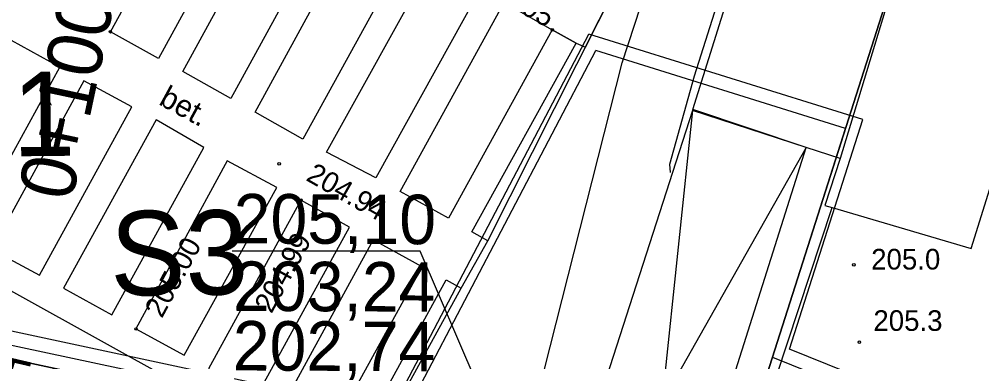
# Model space of a CAD drawing. Extents: x 6512606 to 6513347, y 6022524 to 6022728.
# Drawn here: x 6512758.91 to 6512793.86, y 6022598.41 to 6022610.86 of the extents above; entities that cross this region are included whole.
import ezdxf

# ---------------------------------------------------------------- set-up
doc = ezdxf.new("R2010")
doc.units = 0
for name, color, linetype in [('20', 7, 'Continuous'), ('217-kontur klasyfikacyjny', 7, 'Continuous'), ('218-kontur użytku gruntowego', 7, 'Continuous'), ('219-działka ewidencyjna', 7, 'Continuous'), ('312-budynek ewidencyjny', 7, 'Continuous'), ('4', 7, 'Continuous'), ('996-Tekst dodatkowy mały', 7, 'Continuous'), ('budynek', 7, 'Continuous'), ('chodnik', 7, 'Continuous'), ('chodnik (powierzchnia)', 7, 'Continuous'), ('Default', 7, 'Continuous'), ('kolor_kostka_bet', 7, 'Continuous'), ('Level 47', 7, 'Continuous'), ('maxp_inst_wodociągowa', 7, 'Continuous'), ('maxp_likwidacje', 7, 'Continuous'), ('maxp_ramka_2', 7, 'Continuous'), ('ogrodzenie trwałe', 7, 'Continuous'), ('pikieta naturalna', 7, 'Continuous'), ('pikieta naturalna-Atr2', 7, 'Continuous'), ('pikieta sztuczna', 7, 'Continuous'), ('pikieta sztuczna-Atr2', 7, 'Continuous'), ('przewód elektroenergetyczny (linia)', 7, 'Continuous'), ('przewód kanalizacyjny (linia)', 7, 'Continuous'), ('psr_os', 7, 'Continuous'), ('punkt wysokościowy naturalny', 7, 'Continuous'), ('punkt wysokościowy naturalny-Atr2', 7, 'Continuous'), ('punkt wysokościowy sztuczny', 7, 'Continuous'), ('punkt wysokościowy sztuczny-Atr2', 7, 'Continuous')]:
    doc.layers.add(name, color=color, linetype=linetype)

# ---------------------------------------------------------------- blocks, each defined once
blk = doc.blocks.new('PW01')
at = {"layer": 'Default'}
blk.add_circle((0, 0), 0.45, dxfattribs=at)
blk = doc.blocks.new('PW02')
at = {"layer": 'Default'}
blk.add_circle((0, 0), 0.45, dxfattribs=at)

msp = doc.modelspace()

# ---------------------------------------------------------------- linework, layer by layer
msp.add_line((6512749.181, 6022600.515), (6512804.476, 6022588.74))
at = {"layer": '20'}
for p, q in [((6512773.476, 6022602.425), (6512766.642, 6022602.425)), ((6512777.689, 6022592.612), (6512773.476, 6022602.425))]:
    msp.add_line(p, q, dxfattribs=at)
at = {"layer": '217-kontur klasyfikacyjny'}
msp.add_lwpolyline([(6512784.22, 6022592.17), (6512791.71, 6022615.65)], dxfattribs=at)
at = {"layer": '218-kontur użytku gruntowego'}
for points in [[(6512791.71, 6022615.65), (6512784.22, 6022592.17)], [(6512784.22, 6022592.17), (6512791.71, 6022615.65)]]:
    msp.add_lwpolyline(points, dxfattribs=at)
at = {"layer": '219-działka ewidencyjna'}
msp.add_lwpolyline([(6512791.71, 6022615.65), (6512784.22, 6022592.17)], dxfattribs=at)
at = {"layer": '312-budynek ewidencyjny'}
for points in [[(6512788.72, 6022605.79), (6512787.49, 6022606.19), (6512783.37, 6022607.57), (6512787.17, 6022619.72), (6512788.71, 6022624.64), (6512794.05, 6022622.97), (6512792.55, 6022618.27), (6512791.71, 6022615.65)], [(6512794.05, 6022622.97), (6512792.55, 6022618.27), (6512791.71, 6022615.65), (6512788.72, 6022605.79), (6512788.17, 6022604.09), (6512788.43, 6022604.01), (6512793.48, 6022602.52), (6512799.35, 6022621.32)]]:
    msp.add_lwpolyline(points, close=True, dxfattribs=at)
at = {"layer": '4'}
msp.add_lwpolyline([(6512791.71, 6022615.65), (6512784.22, 6022592.17)], dxfattribs=at)
at = {"layer": 'budynek'}
msp.add_lwpolyline([(6512776.87, 6022587.41), (6512781.1, 6022585.98), (6512787.49, 6022606.19), (6512783.36, 6022607.54)], close=True, dxfattribs=at)
at = {"layer": 'chodnik'}
msp.add_lwpolyline([(6512776.52, 6022611.46), (6512778.27, 6022610.47), (6512779.14, 6022609.99), (6512779.47, 6022609.84), (6512780.39, 6022611.67)], dxfattribs=at)
at = {"layer": 'chodnik (powierzchnia)'}
for points in [[(6512757.29, 6022622.23), (6512758.16, 6022621.75), (6512759.91, 6022620.76), (6512760.79, 6022620.25), (6512762.54, 6022619.28), (6512763.4, 6022618.8), (6512765.15, 6022617.82), (6512766.04, 6022617.34), (6512767.77, 6022616.38), (6512768.63, 6022615.88), (6512770.38, 6022614.9), (6512771.24, 6022614.38), (6512773.01, 6022613.42), (6512773.89, 6022612.93), (6512775.64, 6022611.93), (6512776.52, 6022611.46), (6512778.27, 6022610.47), (6512779.14, 6022609.99)], [(6512767.77, 6022616.38), (6512763.97, 6022609.43), (6512762.22, 6022610.4), (6512766.04, 6022617.34)], [(6512770.38, 6022614.9), (6512766.6, 6022607.98), (6512764.85, 6022608.96), (6512768.63, 6022615.88)], [(6512773.01, 6022613.42), (6512769.21, 6022606.5), (6512767.48, 6022607.48), (6512771.24, 6022614.38)], [(6512752.5, 6022613.48), (6512749.14, 6022607.36), (6512747.64, 6022608.16), (6512747.15, 6022607.34), (6512770.57, 6022594.35), (6512774.41, 6022601.39), (6512774.96, 6022601.08), (6512775.93, 6022602.8), (6512775.35, 6022603.13), (6512779.14, 6022609.99), (6512778.27, 6022610.47), (6512774.5, 6022603.63), (6512772.74, 6022604.6), (6512776.52, 6022611.46)], [(6512775.64, 6022611.93), (6512771.86, 6022605.09), (6512770.07, 6022606.02), (6512773.89, 6022612.93)]]:
    msp.add_lwpolyline(points, dxfattribs=at)
for points in [[(6512758.63, 6022610.08), (6512755.27, 6022603.96), (6512757.03, 6022603.01), (6512760.39, 6022609.12)], [(6512761.26, 6022608.62), (6512757.9, 6022602.49), (6512759.65, 6022601.56), (6512763, 6022607.67)], [(6512763.88, 6022607.2), (6512760.52, 6022601.08), (6512762.28, 6022600.11), (6512765.62, 6022606.2)], [(6512766.46, 6022605.71), (6512763.15, 6022599.6), (6512764.9, 6022598.65), (6512768.27, 6022604.74)], [(6512769.14, 6022604.28), (6512765.78, 6022598.15), (6512767.54, 6022597.17), (6512770.9, 6022603.3)], [(6512771.77, 6022602.84), (6512768.4, 6022596.67), (6512770.17, 6022595.71), (6512773.54, 6022601.86)]]:
    msp.add_lwpolyline(points, close=True, dxfattribs=at)
at = {"layer": 'kolor_kostka_bet'}
msp.add_line((6512804.476, 6022588.74), (6512749.181, 6022600.515), dxfattribs=at)
at = {"layer": 'maxp_likwidacje'}
for p, q in [((6512783.36, 6022607.54), (6512781.1, 6022585.98)), ((6512787.49, 6022606.19), (6512783.359, 6022607.54)), ((6512787.49, 6022606.19), (6512776.87, 6022587.41))]:
    msp.add_line(p, q, dxfattribs=at)
msp.add_lwpolyline([(6512783.36, 6022607.54), (6512776.871, 6022587.41), (6512781.1, 6022585.98), (6512787.49, 6022606.19)], dxfattribs=at)
at = {"layer": 'maxp_ramka_2'}
for p, q in [((6512772.409, 6022596.591), (6512779.598, 6022610.319)), ((6512789.544, 6022607.214), (6512779.598, 6022610.319)), ((6512772.676, 6022596.023), (6512779.847, 6022609.717)), ((6512788.915, 6022606.887), (6512779.847, 6022609.717)), ((6512786.88, 6022598.864), (6512789.544, 6022607.214)), ((6512786.263, 6022598.573), (6512788.915, 6022606.887)), ((6512749.728, 6022601.421), (6512772.409, 6022596.591)), ((6512749.285, 6022601.004), (6512804.509, 6022589.244))]:
    msp.add_line(p, q, dxfattribs=at)
for points in [[(6512799.94, 6022590.728), (6512800.503, 6022593.371), (6512786.88, 6022598.864)], [(6512786.263, 6022598.573), (6512799.926, 6022593.065), (6512799.451, 6022590.832)]]:
    msp.add_lwpolyline(points, dxfattribs=at)
at = {"layer": 'ogrodzenie trwałe'}
for points in [[(6512744.3, 6022605.68), (6512748.08, 6022603.68), (6512764.51, 6022594.96), (6512770, 6022592.05), (6512774.96, 6022601.08), (6512775.93, 6022602.8), (6512779.97, 6022610.83), (6512780.39, 6022611.67), (6512774.54, 6022615.22)], [(6512784.68, 6022576), (6512784.58, 6022577.92), (6512786.48, 6022581.91), (6512782.06, 6022584.86), (6512783.19, 6022588.03), (6512784.8, 6022593), (6512788.43, 6022604.01)]]:
    msp.add_lwpolyline(points, dxfattribs=at)
at = {"layer": 'przewód elektroenergetyczny (linia)'}
msp.add_lwpolyline([(6512782.56, 6022605.29), (6512782.54, 6022605.59), (6512783.43, 6022608.8), (6512786.9, 6022619.73), (6512788.66, 6022625.18), (6512788.94, 6022625.46)], dxfattribs=at)
at = {"layer": 'przewód kanalizacyjny (linia)'}
msp.add_lwpolyline([(6512771.21, 6022579.63), (6512775.79, 6022589.49), (6512780.81, 6022609.27), (6512784.81, 6022621.53)], dxfattribs=at)

# ---------------------------------------------------------------- block references
at = {"layer": 'pikieta naturalna', "xscale": 0.1, "yscale": 0.10000000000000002}
msp.add_blockref('PW01', (6512789.42, 6022599.12), dxfattribs=at)
at = {"layer": 'pikieta sztuczna', "xscale": 0.1, "yscale": 0.10000000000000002}
msp.add_blockref('PW01', (6512768.35, 6022605.6), dxfattribs=at)
at = {"layer": 'punkt wysokościowy naturalny', "xscale": 0.1, "yscale": 0.10000000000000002}
msp.add_blockref('PW01', (6512789.22, 6022601.93), dxfattribs=at)
at = {"layer": 'punkt wysokościowy sztuczny', "xscale": 0.1, "yscale": 0.10000000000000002}
for p in [(6512762.22, 6022610.4), (6512778.27, 6022610.47), (6512769.14, 6022604.28), (6512763.15, 6022599.6)]:
    msp.add_blockref('PW02', p, dxfattribs=at)

# ---------------------------------------------------------------- texts
at = {"layer": '996-Tekst dodatkowy mały'}
msp.add_text(' bet.', height=0.8, rotation=331.366, dxfattribs=at).set_placement((6512763.68, 6022607.92))
at = {"layer": 'Level 47'}
for s, height, rotation, p in [('205,10', 1.7971, 359.7281, (6512766.695, 6022602.713)), ('203,24', 1.7971, 359.7281, (6512766.673, 6022600.259)), ('202,74', 1.7971, 359.7281, (6512766.663, 6022598.094)), ('315 PP', 1.3824, 346.919, (6512756.175, 6022597.699))]:
    msp.add_text(s, height=height, rotation=rotation, dxfattribs=at).set_placement(p)
at = {"layer": 'maxp_inst_wodociągowa'}
for s, p in [('S1', (6512755.936, 6022605.845)), ('S3', (6512762.223, 6022600.809))]:
    msp.add_text(s, height=3.0671, rotation=0.5777, dxfattribs=at).set_placement(p)
at = {"layer": 'pikieta naturalna-Atr2'}
msp.add_text('205.3', height=0.75, dxfattribs=at).set_placement((6512789.93, 6022599.53))
at = {"layer": 'pikieta sztuczna-Atr2'}
msp.add_text('204.94', height=0.75, rotation=330.376, dxfattribs=at).set_placement((6512769.29, 6022605.02))
at = {"layer": 'psr_os'}
msp.add_text('0+100.00', height=2, rotation=77.9783, dxfattribs=at).set_placement((6512760.817, 6022604.19))
at = {"layer": 'punkt wysokościowy naturalny-Atr2'}
msp.add_text('205.0', height=0.75, dxfattribs=at).set_placement((6512789.85, 6022601.76))
at = {"layer": 'punkt wysokościowy sztuczny-Atr2'}
for s, rotation, p in [('204.95', 330.255, (6512775.41, 6022612.06)), ('204.99', 61.272, (6512768.07, 6022600.13)), ('205.00', 61.554, (6512764.09, 6022599.96))]:
    msp.add_text(s, height=0.75, rotation=rotation, dxfattribs=at).set_placement(p)

doc.saveas('drawing.dxf')
